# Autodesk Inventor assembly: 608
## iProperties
Shininess: 64.0
Length Units: 11269
Angle Units: 11279
Time Units: 11290
Mass Units: 11283
Length Display Precision: 3
Angle Display Precision: 2
Compacted: True
Created: 2004-09
Part Number: 608
Document SubType Name: Assembly
Density: 0.0
Volumn: 0.0
Area: 0.0
PropertySet Name: Model Information
Control State: 0
Master: False
Checked Out: False
